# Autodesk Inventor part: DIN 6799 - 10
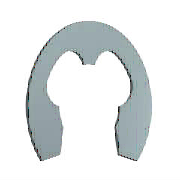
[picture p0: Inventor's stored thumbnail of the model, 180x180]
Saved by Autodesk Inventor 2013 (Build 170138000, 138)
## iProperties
Created: 2012-02
Part Number: DIN 6799 - 10
Material: Stahl, weich
Description: Sicherungsscheibe
Document SubType Name: Modeling
Standard: DIN 6799
Designer: macuser
Standards Organization: DIN
Language: de-DE
Size Designation: 10
Categories: <MemberInstance><Categories><Category DisplayName="Wellenteile" InternalName="7f7aeb1f-a693-4053-b835-cee3144e0d98" Mnemonic="SHFT"><Category DisplayName="Siche
Density: 1 g/cm^3
IsCustomPart: 0
Author: macuser
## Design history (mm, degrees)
sketch "Skizze1"
  geometry: L1 (-1, 0.024)-(0, 0.024) reference; L2 (-3.206, 0)-(3.486, 0) reference; L3 (-4.583, -7.476)-(4.583, -7.476); L4 (0, 1.949)-(0, -3.479) reference; L5 (-6, -3.476)-(-5.02, -3.476); L6 (-1, 0.524)-(-1, 1.495); L7 (0, 4.724)-(2.53, 4.724); L8 (-4.583, -7.476)-(-5.839, -10.822); L9 (0, -0.476)-(-1.278, -0.476); L10 (4.583, -7.476)-(5.839, -10.822); L11 (6, -3.476)-(5.02, -3.476); L12 (1, 0.524)-(1, 1.495); C1 r 5.5 at (0, -5.476); A1 r 5 centre (0, -5.476) between (-4.736, -3.873) and (-4.583, -7.476); A2 r 1 centre (0, 0.524) between (-1, 0.524) and (1, 0.524); A3 r 10.2 centre (0, -5.476) between (8.493, -11.126) and (-8.493, -11.126); A4 r 8 centre (0, -5.476) between (-2, 2.27) and (-7.059, -1.712); A5 r 0.8 centre (-1.8, 1.495) between (-1, 1.495) and (-2, 2.27); A6 r 1.2 centre (-6, -2.276) between (-7.059, -1.712) and (-6, -3.476); A7 r 0.3 centre (-5.02, -3.776) between (-4.736, -3.873) and (-5.02, -3.476); A8 r 1.5 centre (-7.244, -10.295) between (-8.493, -11.126) and (-5.839, -10.822); A9 r 1.5 centre (7.244, -10.295) between (5.839, -10.822) and (8.493, -11.126); A10 r 5 centre (0, -5.476) between (4.583, -7.476) and (4.736, -3.873); A11 r 0.3 centre (5.02, -3.776) between (5.02, -3.476) and (4.736, -3.873); A12 r 1.2 centre (6, -2.276) between (6, -3.476) and (7.059, -1.712); A13 r 8 centre (0, -5.476) between (7.059, -1.712) and (2, 2.27); A14 r 0.8 centre (1.8, 1.495) between (2, 2.27) and (1, 1.495); 1 further point
  constraints: 30 point on circle, 20 end point, 15 centre point, 13 symmetric about line, 12 tangent, 8 point on line, 4 parallel, 2 coincident, 2 horizontal, 1 concentric, 1 perpendicular, 1 vertical alignment, 9 other
  dimensions: "d0" = 11 diameter of C1 (= WD); "d3" = 2 distance from line of A1.centre L3 (= 0.2 x ND); "d4" = 1 radius of A2 (= 0.1 x ND); "d5" = 20.4 diameter of A3 (= SD2); "d8" = 8 radius of A4 (= 0.8 x ND); "d9" = 2 distance from line of A1.centre L5 (= 0.2 x ND); "d10" = 0.8 radius of A5 (= 0.08 x ND); "d11" = 1.2 radius of A6 (= 0.12 x ND); "d12" = 0.3 radius of A7 (= 0.03 x ND); "d13" = 1.5 radius of A8 (= 0.15 x ND); "d14" = 5 distance from line of A1.centre L9 (= 0.5 x ND); "d15" = 5 radius of A1 (= 0.5 x ND)
extrude "Körper" new body sketch "Skizze1" distance "d16" = 1.2 (= SD); taper "d17" = 0 deg
workaxis "Work Axis1"
workaxis "Work Axis2"
workplane "Work Plane1"
body "Solid1"
other parameters: "SD" = 1.2 [user parameter; used in 1 equation term], "WD" = 11 [user parameter; used in 1 equation term], "d1" = 16 (= 1.6 x ND), "SD2" = 20.4 [user parameter; used in 1 equation term], "d7" = 1.5 (= 0.15 x ND), "d18" = 0, "d19" = 0, "d27" = 0, "d28" = 0, "SNB" = 1.25 [user parameter], "WDMAX" = 14 [user parameter], "BUBRMI" = 2 [user parameter]
